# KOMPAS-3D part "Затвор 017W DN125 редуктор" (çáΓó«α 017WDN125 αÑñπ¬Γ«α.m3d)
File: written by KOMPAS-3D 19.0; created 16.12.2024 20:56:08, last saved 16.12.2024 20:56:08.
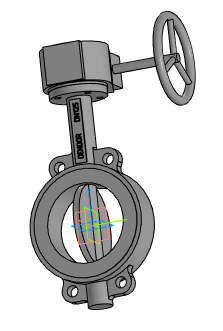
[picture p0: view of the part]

Document properties: Автор: Евгений; Полное имя файла: ..\Затвор 017WDN125 редуктор.a3d

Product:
- Part/product: Затвор 017W DN125 редуктор
    Масса: 16.0553

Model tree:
1. Операция без истории:1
